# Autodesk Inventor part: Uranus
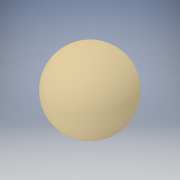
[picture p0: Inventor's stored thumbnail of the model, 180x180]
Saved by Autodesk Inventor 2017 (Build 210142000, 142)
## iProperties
Created: 2016-07
Part Number: Uranus
Material: Generic
Document SubType Name: Modeling
Designer: Stan
Density: 1 g/cm^3
Appearance: Orange
Author: Stan
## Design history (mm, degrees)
sketch "Sketch1"
  geometry: L1 (-3.175, -17.171)-(0, -17.171); L2 (0, 17.463)-(0, -17.171); A1 r 17.463 centre (0, 0) between (0, 17.463) and (-3.175, -17.171); 1 further point
  constraints: 4 end point, 2 point on circle, 1 centre point, 1 coincident, 1 horizontal, 1 perpendicular
  dimensions: "d0" = 34.925 diameter of A1; "d2" = 3.175 distance from line of L1.start L2; "d3" = 0 distance from line of point (0, 0) L2
revolve "Revolution1" sketch "Sketch1" stored, may be unused: angle "d4" = 90 deg
sketch "Sketch2"
  geometry: C1 r 1.587 at (0, 0); 1 further point
  constraints: 1 centre point, 1 coincident
  dimensions: "d5" = 3.175 diameter of C1
extrude "Extrusion1" cut sketch "Sketch2" distance "d6" = 6.35; taper "d7" = 0 deg
body "Solid1"
